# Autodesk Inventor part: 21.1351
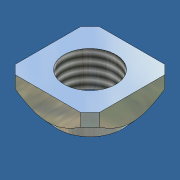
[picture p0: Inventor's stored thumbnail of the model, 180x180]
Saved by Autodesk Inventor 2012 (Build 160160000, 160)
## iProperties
Created: 2006-12
Part Number: 21.1351
Document SubType Name: Modeling
Designer: Andy Moles
Material: Steel, Mild
Mass: 3.99144 g
Surface Area: 5.54975 cm^2
Volume: 0.507817 cm^3
Density: 7.86 g/cm^3
Description: M8 SQUARE NUT
Vendor: S
Author: Andy Moles
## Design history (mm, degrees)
sketch "Sketch2"
  geometry: L1 (-5.086, -6.5)-(5.086, -6.5); L2 (6.5, -5.086)-(6.5, 5.086); L3 (5.086, 6.5)-(-5.086, 6.5); L4 (-6.5, 5.086)-(-6.5, -5.086); L5 (-6.5, 6.5)-(6.5, -6.5); L6 (5.086, 6.5)-(6.5, 5.086); L7 (0, -6.5)-(0, 6.5); L8 (-6.5, 0)-(6.5, 0); L9 (-5.086, 6.5)-(-6.5, 5.086); L10 (-5.086, -6.5)-(-6.5, -5.086); L11 (5.086, -6.5)-(6.5, -5.086); C1 r 4 at (0, 0); 2 further points
  constraints: 22 end point, 6 symmetric about line, 4 parallel, 3 midpoint, 2 coincident, 2 perpendicular, 1 centre point, 1 horizontal
  dimensions: "THREAD" = 8 diameter of C1; "d3" = 45 deg angle of L3 L6 (derived); "d4" = 2 distance of L3.start L2.end
extrude "Extrusion1" new body sketch "Sketch2" distance "d5" = 5.5; taper "d6" = 0 deg
workplane "Work Plane1"
sketch "Sketch4"
  geometry: L1 (12.192, 0)-(4.192, 0) reference; L2 (8.192, 0)-(13.192, 0); L3 (16.385, 5.5)-(16.385, 3.5); L4 (13.192, 0)-(16.797, 3.952); L5 (13.192, 0)-(16.385, 0); L6 (16.385, 3.5)-(16.385, 0); L7 (16.797, 3.952)-(16.797, -0.412); L8 (16.797, -0.412)-(13.192, -0.412); L9 (13.192, -0.412)-(13.192, 0); L10 (8.192, 5.5)-(8.192, 0); L11 (16.385, 5.5)-(16.385, 0) reference; L12 (16.385, 3.5)-(17.502, 3.5); L13 (9.192, 5.5)-(16.385, 5.5) reference
  constraints: 20 end point, 6 perpendicular, 1 collinear, 1 midpoint, 1 parallel, 1 point on line
  dimensions: "d10" = 5 distance of L2.start L2.end; "d15" = 2 distance between parallel lines of L12 L13
revolve "Revolution1" sketch "Sketch4" stored, may be unused: angle "d12" = 90 deg
thread "Thread1" dims "d13" = 10, "d14" = 0
body "Solid1"
